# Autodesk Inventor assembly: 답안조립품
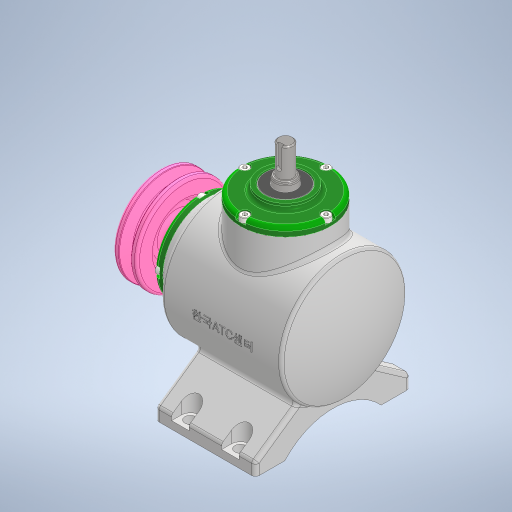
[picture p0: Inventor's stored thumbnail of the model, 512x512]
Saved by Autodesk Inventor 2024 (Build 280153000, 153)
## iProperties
Created: 2023-08
Part Number: 답안조립품
Document SubType Name: Assembly
Designer: Owner
Author: Owner
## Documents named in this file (17)
- C:\Users\Owner\Desktop\730813V1008\답안조립품.iam
- C:\Users\Owner\Desktop\730813V1008\본체.ipt
- C:\Users\Owner\Desktop\730813V1008\V-벨트풀리.ipt
- C:\Users\Owner\Desktop\730813V1008\메인 베벨기어.ipt
- C:\Users\Owner\Desktop\730813V1008\메인 축.ipt
- 메인 축.ipt
- C:\Users\Owner\Desktop\730813V1008\베어링 6203.ipt
- C:\Users\Owner\Desktop\730813V1008\볼트 M4 x 10.ipt
- C:\Users\Owner\Desktop\730813V1008\서브 베벨기어.ipt
- C:\Users\Owner\Desktop\730813V1008\서브 축.ipt
- 서브 축.ipt
- C:\Users\Owner\Desktop\730813V1008\오일실 17 x 32 x 8.ipt
- C:\Users\Owner\Desktop\730813V1008\와셔 4 x 16.ipt
- C:\Users\Owner\Desktop\730813V1008\육각볼트 M4 x 8.ipt
- C:\Users\Owner\Desktop\730813V1008\커버.ipt
- C:\Users\Owner\Desktop\730813V1008\키 4 x 4 x 14.ipt
- C:\Users\Owner\Desktop\730813V1008\키 5 x 5 x 14.ipt
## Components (1 placed, 1 different names)
1. V-벨트풀리:1
